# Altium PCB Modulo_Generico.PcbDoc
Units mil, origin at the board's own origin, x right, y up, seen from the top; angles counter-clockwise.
Board outline 6000 x 4000 mil, 2 copper layers (Top Layer, Bottom Layer); 31 components, 42 nets, 135 pads, 6 vias.
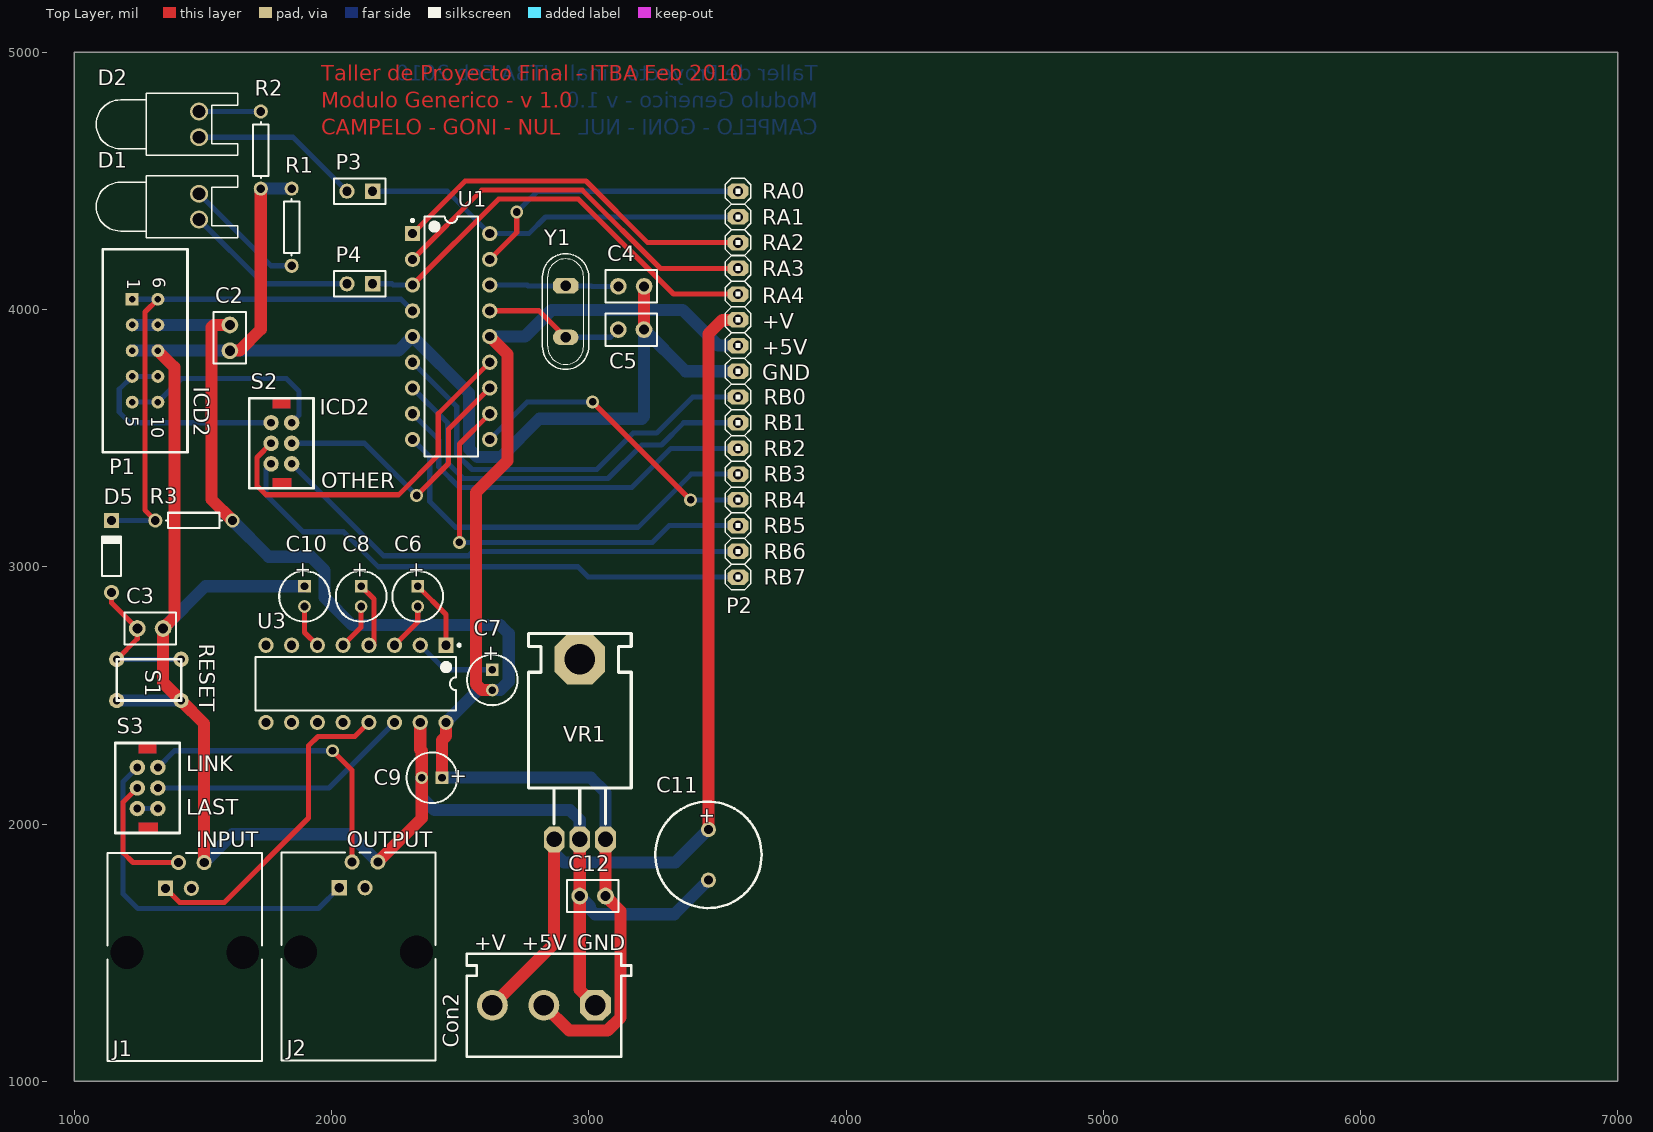
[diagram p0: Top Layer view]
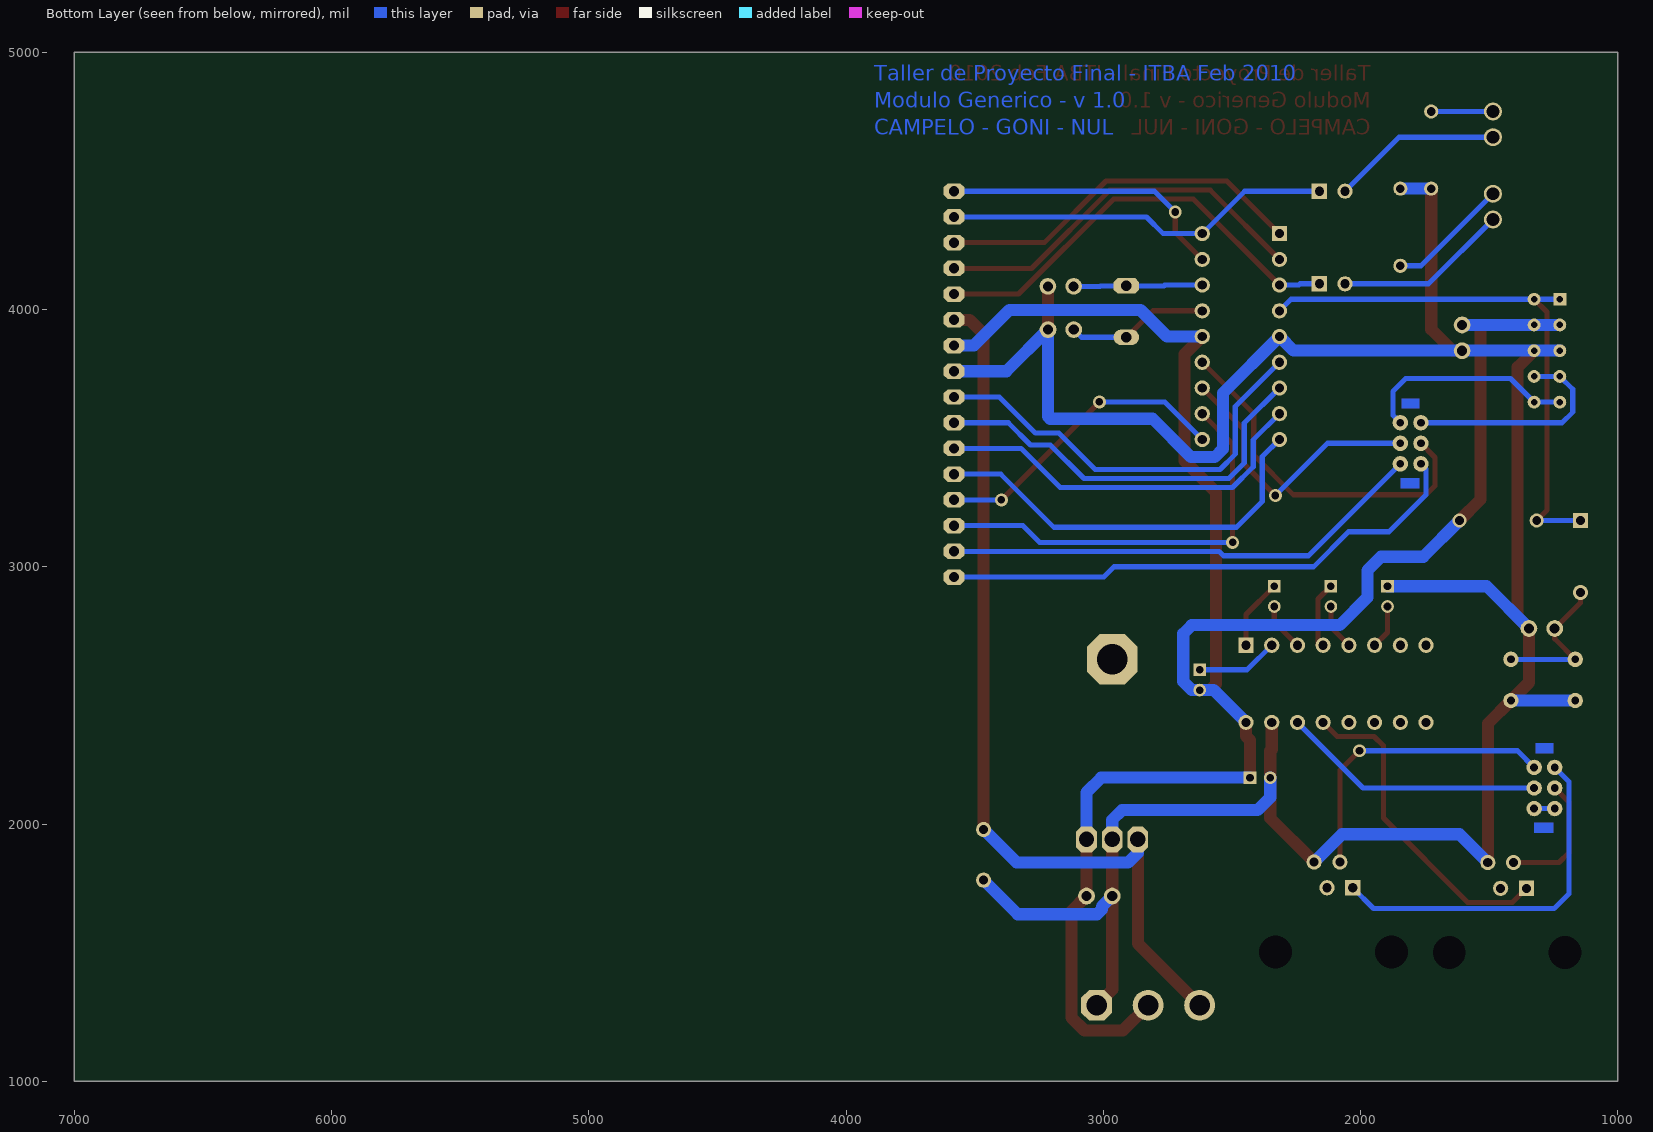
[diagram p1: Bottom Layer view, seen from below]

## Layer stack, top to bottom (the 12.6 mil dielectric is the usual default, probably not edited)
Top Layer: signal copper 1.4
Dielectric: dielectric 12.6, FR-4, Dk 4.8
Bottom Layer: signal copper 1.4

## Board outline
1000,1000 7000,1000 7000,5000 1000,5000

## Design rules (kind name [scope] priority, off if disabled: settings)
Clearance [All] p1: gap=15
DiffPairsRouting [All] p1: maxlimit=10 minlimit=10 mostfreqgap=10 maxuncoupledlength=750
PolygonConnect [All] p1: connectstyle=Relief reliefconductorwidth=10 reliefentries=4 polygonreliefangle="90 Angle"
RoutingVias [All] p1: holewidth=30 width=50 viastyle="Through Hole" minholewidth=30 minwidth=50 maxholewidth=50 maxwidth=70
SilkscreenOverComponentPads [All] p1: minsilkscreentomaskgap=10
SolderMaskExpansion [All] p1: expansion=4
Width Signal [NOT (InNet('+5V VCC') OR InNet('+V LOGIC') OR InNet('GND'))] p1: maxlimit=25 minlimit=15 preferedwidth=20 minimp=50.000000 maximp=50.000000 favimp=50.000000
Width Power [(InNet('+5V VCC') OR InNet('+V LOGIC') OR InNet('GND'))] p2: maxlimit=47 minlimit=47 preferedwidth=47 minimp=50.000000 maximp=50.000000 favimp=50.000000
26 further rules are at their usual default settings.

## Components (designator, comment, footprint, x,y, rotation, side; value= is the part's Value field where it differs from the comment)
C2 "Cap" CAPR2.54-5.1x3.2 1605,3890 r90 top
C3 "Cap" CAPR2.54-5.1x3.2 1295,2760 r180 top
C4 "Cap" CAPR2.54-5.1x3.2 3165,4090 r180 top
C5 "Cap" CAPR2.54-5.1x3.2 3164.61,3922.01 r180 top
C6 "Cap Pol1" CAPPR2-5x6.8 2335,2885 r270 top
C7 "Cap Pol1" CAPPR2-5x6.8 2625,2560 r270 top
C8 "Cap Pol1" CAPPR2-5x6.8 2115,2885 r270 top
C9 "Cap Pol1" CAPPR2-5x6.8 2390,2180 r180 top
C10 "Cap Pol1" CAPPR2-5x6.8 1895,2885 r270 top
C11 "Cap Pol1" RB5-10.5 3465,1880 r270 top
C12 "Cap" CAPR2.54-5.1x3.2 3015,1720 r0 top
Con2 "POWER_A" My_CN3 3125,1095 r180 top
D1 "LED0" LED-0 1485,4400 r270 top
D2 "LED0" LED-0 1485,4720 r270 top
D5 "Diode 1N4148" DIO7.1-3.9x1.9 1145,3040 r90 top
J1 "SERIAL A" 15-43-6245 1430,1077.95 r0 top
J2 "SERIAL B" 15-43-6245 2105,1080 r0 top
P1 "ICD2" HEADER10_5x2_B 1275,3840 r270 top
P2 "Header 16" My_1X16 3580,3710 r270 top
P3 "LED2" HDR1X2 2160,4460 r180 top
P4 "LED1" HDR1X2 2160,4100 r180 top
R1 "Res1" AXIAL-0.3 1845,4320 r90 top
R2 "Res1" AXIAL-0.3 1725,4620 r270 top
R3 "Res1" AXIAL-0.3 1465,3180 r0 top
S1 "SW-PB" TS-063 1290,2560 r270 top
S2 "PROGRAM SELECTION" LD-202mini 1805,3480 r270 top
S3 "SERIAL CHAIN" LD-202mini 1285,2140 r270 top
U1 "PIC16F88" PDIP300-P18 2465,3895 r0 top
U3 "MAX232" PE16A 2095,2545 r270 top
VR1 "7805" My_TO-220 2865.51,1940.51 r0 top
Y1 "20MHz" My_Crystal 2910,3992.01 r270 top

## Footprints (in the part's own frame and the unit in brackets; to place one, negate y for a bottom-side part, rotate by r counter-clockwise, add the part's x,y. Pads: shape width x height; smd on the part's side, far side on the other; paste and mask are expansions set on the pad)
15-43-6245 [mm] "Connector; PCB Jack, Thru-Hole; 1-Port; Unshielded without Lightpipes; Right Angle"
  rect 1.5x1.5 hole 0.9: 1(-1.905,17.07)
  round 1.5 hole 0.9: 2(-0.635,19.61) 3(0.635,17.07) 4(1.905,19.61)
  round 2.95 hole 3.25 unplated: MH1(-5.715,10.72) MH2(5.715,10.72)
  silkscreen extent -7.62,0 7.62,20.57
AXIAL-0.3 [mm] "Axial Device, Thru-Hole; 2 Leads; 0.3 in Pin Spacing"
  round 1.4 hole 0.85: 1(-3.81,0) 2(3.81,0)
  silkscreen extent -2.77,-0.76 2.77,0.76
CAPPR2-5x6.8 [mm] "Capacitor, Electrolytic, Radial; Body 5 x 6.8 mm (Dia.xH typ); Pin Spacing 2 mm (typ)"
  rect 1.25x1.25 hole 0.75: 1(-1,0)
  round 1.25 hole 0.75: 2(1,0)
  silkscreen extent -2.5,-2.5 2.5,2.5
CAPR2.54-5.1x3.2 [mm] "Capacitor, Ceramic, Thru-Hole, Dipped Radial; Body 5.1 x 3.2 mm (WxT) Pin Spacing 2.54 mm (typ)"
  round 1.65 hole 1: 1(-1.27,0) 2(1.27,0)
  silkscreen extent -2.55,-1.6 2.55,1.6
DIO7.1-3.9x1.9 [mm] "Diode, Axial; Body 3.8 x 1.9 mm (LxDia. max), Lead Dia. 0.53 mm (max)"
  round 1.5 hole 0.9: 1(-3.55,0)
  rect 1.5x1.5 hole 0.9: 2(3.55,0)
  silkscreen extent -1.95,-0.95 2.05,0.95
HDR1X2 [mm] "Connector; Header; 2 Position"
  rect 1.5x1.5 hole 0.9: 1(0,0)
  round 1.5 hole 0.9: 2(2.54,0)
  silkscreen extent -1.27,-1.27 3.81,1.27
HEADER10_5x2_B [mil] "Header con polaridad para 10 pines (5x2)"
  rect 50x50 hole 25: 1(-200,-50)
  round 50 hole 25: 2(-100,-50) 3(0,-50) 4(100,-50) 5(200,-50) 6(-200,50) 7(-100,50) 8(0,50) 9(100,50) 10(200,50)
  silkscreen extent -395,-165 395,165
LD-202mini [mil] "Doble inversor mini 90 grados"
  round 60 hole 30: 1(0,40) 2(-80,40) 3(80,40) 4(0,-40) 5(-80,-40) 6(80,-40)
  Multi-Layer region: 135,-35 175,-35 175,40 135,40
  Multi-Layer region: -175,-35 -135,-35 -135,35 -175,35
  silkscreen extent -175,-125 175,125
LED-0 [mil] "Typical INFRARED GaAs LED; 2 Leads"
  round 70 hole 50: 1(50,0) 2(-50,0)
  silkscreen extent -120,-400 120,150
My_1X16 [mil]
  oct 60x80 hole 40: 1(-750,0) 2(-650,0) 3(-550,0) 4(-450,0) 5(-350,0) 6(-250,0) 7(-150,0) 8(-50,0) 9(50,0) 10(150,0) 11(250,0) 12(350,0) 13(450,0) 14(550,0) 15(650,0) 16(750,0)
  silkscreen extent -800,-50 800,50
My_CN3 [mil]
  oct 120x120 hole 80: 1(99.5,-200.5)
  round 120 hole 80: 2(299.5,-200.5) 3(499.5,-200.5)
  silkscreen extent -40,-400 600,0
My_Crystal [mil]
  oct 60x100 hole 40: 1(-100,0)
  oval 60x100 hole 40: 2(100,0)
  silkscreen extent -225,-90 225,90
My_TO-220 [mil]
  oct 196.85x196.85 hole 118.11: 0(99.49,699.49)
  oct 80x100 hole 60: 1(-0.5,-0.5) 2(99.5,-0.5) 3(199.5,-0.5)
  silkscreen extent -100,60 300,800
PDIP300-P18 [mm] "DIP, 18-Leads, Row Spacing 7.62mm, Pitch 2.54mm, Body 22.9x6.6mm"
  rect 1.5x1.5 hole 0.9: 1(-3.81,10.16)
  round 1.5 hole 0.9: 2(-3.81,7.62) 3(-3.81,5.08) 4(-3.81,2.54) 5(-3.81,0) 6(-3.81,-2.54) 7(-3.81,-5.08) 8(-3.81,-7.62) 9(-3.81,-10.16) 10(3.81,-10.16) 11(3.81,-7.62) 12(3.81,-5.08) 13(3.81,-2.54) 14(3.81,0) 15(3.81,2.54) 16(3.81,5.08) 17(3.81,7.62) 18(3.81,10.16)
  silkscreen extent -3.93,-11.85 2.65,11.85, body extent -3.6,-11.8 3.6,11.8, height 5.34
PE16A [mm] "DIP, 16-Leads, Row Spacing 7.62mm, Pitch 2.54mm, Body 19.18x6.99mm"
  rect 1.5x1.5 hole 0.9: 1(-3.81,8.89)
  round 1.5 hole 0.9: 2(-3.81,6.35) 3(-3.81,3.81) 4(-3.81,1.27) 5(-3.81,-1.27) 6(-3.81,-3.81) 7(-3.81,-6.35) 8(-3.81,-8.89) 9(3.81,-8.89) 10(3.81,-6.35) 11(3.81,-3.81) 12(3.81,-1.27) 13(3.81,1.27) 14(3.81,3.81) 15(3.81,6.35) 16(3.81,8.89)
  silkscreen extent -3.93,-9.9 2.65,10.32, body extent -3.3,-9.9 3.3,9.9, height 5.08
RB5-10.5 [mm] "Motor, General Kind; 2 Leads"
  round 1.5 hole 0.9: 1(-2.5,0) 2(2.5,0)
  silkscreen extent -5.25,-5.25 5.25,5.25
TS-063 [mil] "Boton normal abierto"
  round 60 hole 30: 1(80,125) 1(80,-125) 2(-80,125) 2(-80,-125)
  silkscreen extent -80,-125 80,125

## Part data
C2 C3 C4 C5 C12: "Capacitor"
C6 C7 C8 C9 C10 C11: "Polarized Capacitor (Radial)"
Con2: library part "CON3 pin Green", "Connector green screw"
D1 D2: "Typical INFRARED GaAs LED"
D5: "High Conductance Fast Diode"
J1 J2: library part 15-43-6245, "Right Angle, Standard Profile, RJ45-Keyed, Flange Mount PCB Jack"
P1: library part "Header 5X2A", "Header, 5-Pin, Dual row"
P2: "Header, 16-Pin"
P3 P4: library part "Header 2", "Header, 2-Pin"
R1 R2 R3: "Resistor"
S1: "Switch"
S2 S3: library part SW-DPDT, "Double-Pole, Double-Throw Switch"
U1: library part PIC16F88-E/P, "Enhanced FLASH Microcontroller with nanoWatt Technology, 10-Bit A/D, 4K (x14-Bit words) FLASH, 368 Bytes RAM, 18-Pin PDIP, Standard VDD Range, Extended Temperature"
U3: library part MAX232ACPE, "+5V Powered, Multi-Channel RS-232 Driver/Receiver"
VR1: library part "Volt Reg", "Voltage Regulator"
Y1: library part XTAL, "Crystal Oscillator"

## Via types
v1: diameter 50, hole 30, Top Layer to Bottom Layer, 6 vias

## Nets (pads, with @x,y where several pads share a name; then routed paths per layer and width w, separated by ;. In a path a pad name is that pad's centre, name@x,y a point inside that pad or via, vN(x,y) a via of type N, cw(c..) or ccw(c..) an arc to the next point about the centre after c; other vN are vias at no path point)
"+5V VCC": C2.2 C7.2 C9.1 C12.2 Con2.2 P1.2 P1.7 P2.7 R3.2 U1.14 U3.16 VR1.3 | length 7762.7
  Top Layer w47: C2.2 1543,3940 1534,3931 1534,3261 R3.2 ; C9.1 2429.37,2325.74 2445,2341.37 U3.16 ; U1.14 2684,3826 2684,3412 2561,3289 2561,2544 2584.37,2520.63 C7.2 ; Con2.2 2924,1197 3073,1197 3124,1248 3124,1661 C12.2 3065,1830 VR1.3
  Bottom Layer w47: P1.2 P1.7 C2.2 ; R3.2 1756,3039 1920,3039 1973,2986 1973,2881 2081,2773 2656,2773 2689,2740 2689,2553.63 2656,2520.63 C7.2 2570.63,2520.63 U3.16 ; C9.1 3008.01,2180 3065.01,2123 VR1.3 ; U1.14 2752,3895 2855,3998 3365,3998 3503,3860 P2.7
"+V LOGIC": C11.1 Con2.3 P2.6 VR1.1 | length 3529
  Top Layer w47: Con2.3 2865.01,1535.01 VR1.1 ; C11.1 3465,3905 3520,3960 P2.6
  Bottom Layer w47: VR1.1 2865.01,1888 2903.01,1850 3336.57,1850 C11.1
GND: C2.1 C3.1 C4.1 C5.1 C9.2 C10.1 C11.2 C12.1 Con2.1 J1.4 J2.4 P1.3 P1.8 P2.8 R1.2 R2.2 S1.1 U1.5 U3.15 VR1.2 | length 10573.3
  Top Layer w47: P1.8 1389,3776 1389,2804 C3.1 1345,2550 1415,2480 1505,2390 J1.4 ; C2.1 1642,3840 1725,3923 R2.2 ; J2.4 2350.63,2022.68 C9.2 2350.63,2284 2345,2289.63 U3.15 ; VR1.2 2965.01,1830.01 C12.1 2965,1356 Con2.1 ; C5.1 3215,3961.8 C4.1
  Bottom Layer w47: S1.1@1165,2480 S1.1@1415,2480 ; P1.3 P1.8 C2.1 2260,3840 U1.5 2535.1,3674.9 2535.1,3457.9 2566.68,3426.32 2658.58,3426.32 2807.76,3575.5 3206.11,3575.5 3214.61,3584 C5.1 3376.61,3760 P2.8 ; C3.1 1509.37,2924.37 C10.1 ; J1.4 1615,1960 2072.05,1960 J2.4 ; R2.2 R1.2 ; C9.2 2350.63,2103.37 2400,2054 2927.01,2054 2965.01,2016 VR1.2 ; C12.1 3005,1680 3005,1668 3024,1649 3332.43,1649 C11.2
ICD2_CLK: P1.5 P1.10 S2.2 | length 841.8
  Bottom Layer w20: P1.5 P1.10 1417,3732 1824,3732 1874,3682 1874,3589 S2.2
ICD2_CLK/RB6: S2.1 U1.12 | length 1105.7
  Top Layer w20: v1(2331,3277) 2455,3401 2455,3535 U1.12
  Bottom Layer w20: S2.1 2128,3480 v1(2331,3277)
ICD2_DATA: P1.4 P1.9 S2.5 | length 866.7
  Bottom Layer w20: P1.9 P1.4 1175,3690 1175,3601 1216,3560 S2.5
ICD2_DATA/RB7: S2.4 U1.13 | length 1414.9
  Top Layer w20: S2.4 1710,3425 1710,3315 1745,3280 2261.01,3280 2415,3433.99 2415,3595 U1.13
LED1: D1.1 P4.2 | length 678.6
  Bottom Layer w20: D1.1 1735,4100 P4.2
LED2: D2.1 P3.2 | length 662
  Bottom Layer w20: D2.1 1850,4670 P3.2
MAX_TX: S3.1 U3.14 | length 1025.6
  Bottom Layer w20: S3.1 1990,2140 U3.14
MCLR: D5.2 P1.1 P1.6 R3.1 U1.4 | length 2176
  Top Layer w20: R3.1 1275,3220 1275,3990 P1.6
  Bottom Layer w20: D5.2 1229,3179.76 1229.24,3180 R3.1 ; P1.1 P1.6 2270,4040 U1.4
NetC3_2: C3.2 D5.1 S1.2 | length 584.8
  Top Layer w20: D5.1 1145,2860 C3.2 1245,2720 S1.2@1165,2640
  Bottom Layer w20: S1.2@1165,2640 S1.2@1415,2640
NetC4_2: C4.2 U1.16 Y1.1 | length 502.1
  Bottom Layer w20: U1.16 2761,4095 2763.99,4092.01 Y1.1 3011,4092.01 3013.01,4090 C4.2
NetC5_2: C5.2 U1.15 Y1.2 | length 554.7
  Top Layer w20: U1.15 2807.01,3995 Y1.2
  Bottom Layer w20: Y1.2 3084.61,3892.01 C5.2
NetC6_1: C6.1 U3.1 | length 274.9
  Top Layer w20: C6.1 2445,2814.37 U3.1
NetC6_2: C6.2 U3.3 | length 187.9
  Top Layer w20: U3.3 2335,2785 C6.2
NetC7_1: C7.1 U3.2 | length 319.6
  Bottom Layer w20: U3.2 2440.63,2599.37 C7.1
NetC8_1: C8.1 U3.4 | length 270.1
  Top Layer w20: C8.1 2165,2874.37 2165,2695 U3.4
NetC8_2: C8.2 U3.5 | length 179.6
  Top Layer w20: U3.5 2115,2765 C8.2
NetC10_2: C10.2 U3.6 | length 171.3
  Top Layer w20: C10.2 1895,2745 U3.6
NetD1_2: D1.2 R1.1 | length 476
  Bottom Layer w20: D1.2 1765,4170 R1.1
NetD2_2: D2.2 R2.1 | length 240
  Bottom Layer w20: D2.2 R2.1
NetS3_3: S3.3 S3.6 | length 80
  Bottom Layer w20: S3.6 S3.3
PIC_RX: U3.12
PIC_TX: U3.11
RA0: P2.1 U1.17 | length 1121
  Top Layer w20: U1.17 2720,4300 v1(2720,4379)
  Bottom Layer w20: v1(2720,4379) 2801,4460 P2.1
RA1: P2.2 P3.1 U1.18 | length 1515.3
  Bottom Layer w20: P3.1 2450,4460 U1.18 2767,4295 2832,4360 P2.2
RA2: P2.3 U1.1 | length 1449.3
  Top Layer w20: U1.1 2520,4500 2989,4500 3229,4260 P2.3
RA3: P2.4 U1.2 | length 1502.3
  Top Layer w20: U1.2 2584,4464 2975,4464 3279,4160 P2.4
RA4: P2.5 P4.1 U1.3 | length 1713.3
  Top Layer w20: U1.3 2649,4429 2960,4429 3329,4060 P2.5
  Bottom Layer w20: P4.1 2235,4100 2240,4095 U1.3
RB0: P2.9 U1.6 | length 1663.4
  Bottom Layer w20: U1.6 2486.6,3623.4 2486.6,3437.81 2546.59,3377.82 3030.82,3377.82 3172.52,3519.52 3264,3519.52 3404.48,3660 P2.9
RB1: P2.10 U1.7 | length 1591.7
  Bottom Layer w20: U1.7 2451.6,3558.4 2451.6,3403.22 2512,3342.82 3075.28,3342.82 3206.01,3473.55 3282.8,3473.55 3369.25,3560 P2.10
RB2: P2.11 U1.8 | length 1508.3
  Bottom Layer w20: U1.8 2416.6,3493.4 2416.6,3388.65 2497.43,3307.82 3166.82,3307.82 3319,3460 P2.11
RB3: P2.12 U1.9 | length 1594.1
  Bottom Layer w20: U1.9 2381.6,3428.4 2381.6,3253.97 2481.95,3153.62 3192,3153.62 3398.38,3360 P2.12
RB4: P2.13 U1.10 | length 1183.3
  Top Layer w20: v1(3015,3641) v1(3396,3260)
  Bottom Layer w20: U1.10 2761,3641 v1(3015,3641) ; v1(3396,3260) P2.13
RB5: P2.14 U1.11 | length 1658.8
  Top Layer w20: v1(2497,3095) 2497,3477 U1.11
  Bottom Layer w20: v1(2497,3095) 3248,3095 3313,3160 P2.14
RB6: P2.15 S2.3 | length 1890.3
  Bottom Layer w20: S2.3 2202.4,3042.6 2533,3042.6 2550.4,3060 P2.15
RB7: P2.16 S2.6 | length 2095.8
  Bottom Layer w20: S2.6 1745,3380 1745,3280 1889,3136 2046,3136 2182,3000 2958,3000 2998,2960 P2.16
SERIAL_A_RX: J1.2 S3.4 | length 505.5
  Top Layer w20: S3.4 1190,2085 1190,1888 1228,1850 J1.2
SERIAL_A_TX: J1.1 U3.13 | length 1267.3
  Top Layer w20: J1.1 1410,1695 1583,1695 1911,2023 1911,2304 1947,2340 2090,2340 U3.13
SERIAL_B_RX: J2.2 S3.2 | length 1170.4
  Top Layer w20: v1(2004,2285) 2080,2209 J2.2
  Bottom Layer w20: S3.2 1390,2285 v1(2004,2285)
SERIAL_B_TX: J2.1 S3.5 | length 1412
  Bottom Layer w20: S3.5 1190,2165 1190,1728 1247,1671 1948.95,1671 J2.1
pads on no net: J1.3 J1.MH1 J1.MH2 J2.3 J2.MH1 J2.MH2 U3.7 U3.8 U3.9 U3.10 VR1.0

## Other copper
Top Layer:
  text "Taller de Proyecto Final - ITBA Feb 2010" at 1960,4890 h60
  text "Modulo Generico - v 1.0" at 1960,4785 h60
  text "CAMPELO - GONI - NUL" at 1960,4680 h60
Bottom Layer:
  text "Taller de Proyecto Final - ITBA Feb 2010" at 3890,4890 h60
  text "Modulo Generico - v 1.0" at 3890,4785 h60
  text "CAMPELO - GONI - NUL" at 3890,4680 h60

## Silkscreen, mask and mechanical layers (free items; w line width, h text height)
Top Overlay:
  text "RA0" at 3675,4430 h60
  text "RA1" at 3675,4330 h60
  text "RA2" at 3675,4230 h60
  text "RA3" at 3675,4130 h60
  text "RA4" at 3675,4025 h60
  text "+V" at 3675,3925 h60
  text "+5V" at 3675,3825 h60
  text "GND" at 3675,3725 h60
  text "RB0" at 3680,3630 h60
  text "ICD2" at 1955,3590 h60
  text "RB1" at 3680,3530 h60
  text "RB2" at 3680,3430 h60
  text "RB3" at 3680,3330 h60
  text "OTHER" at 1960,3305 h60
  text "RB4" at 3680,3230 h60
  text "RB5" at 3680,3130 h60
  text "RB6" at 3680,3030 h60
  text "RB7" at 3680,2930 h60
  text "RESET" at 1485,2700 h60 r270
  text "LINK" at 1435,2205 h60
  text "LAST" at 1435,2035 h60
  text "INPUT" at 1475,1910 h60
  text "OUTPUT" at 2060,1910 h60
  text "+V" at 2555,1510 h60
  text "+5V" at 2740,1510 h60
  text "GND" at 2955,1510 h60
